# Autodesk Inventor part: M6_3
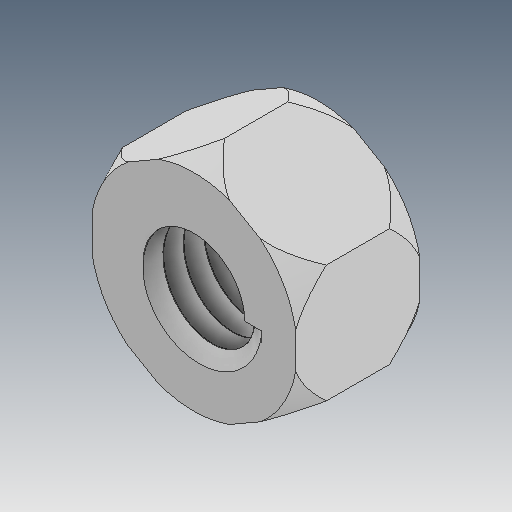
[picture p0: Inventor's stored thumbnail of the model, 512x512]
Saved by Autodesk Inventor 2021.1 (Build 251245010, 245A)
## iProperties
Created: 2019-05
Part Number: M6_3
Material: Ogólny
Document SubType Name: Modeling
Designer: user
Density: 1 g/cm^3
Appearance: Domyślna
Author: user
Revision Number: ÈÎºÎ
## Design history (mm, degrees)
feature "ÊäÈë1"
node "Bryła1"
